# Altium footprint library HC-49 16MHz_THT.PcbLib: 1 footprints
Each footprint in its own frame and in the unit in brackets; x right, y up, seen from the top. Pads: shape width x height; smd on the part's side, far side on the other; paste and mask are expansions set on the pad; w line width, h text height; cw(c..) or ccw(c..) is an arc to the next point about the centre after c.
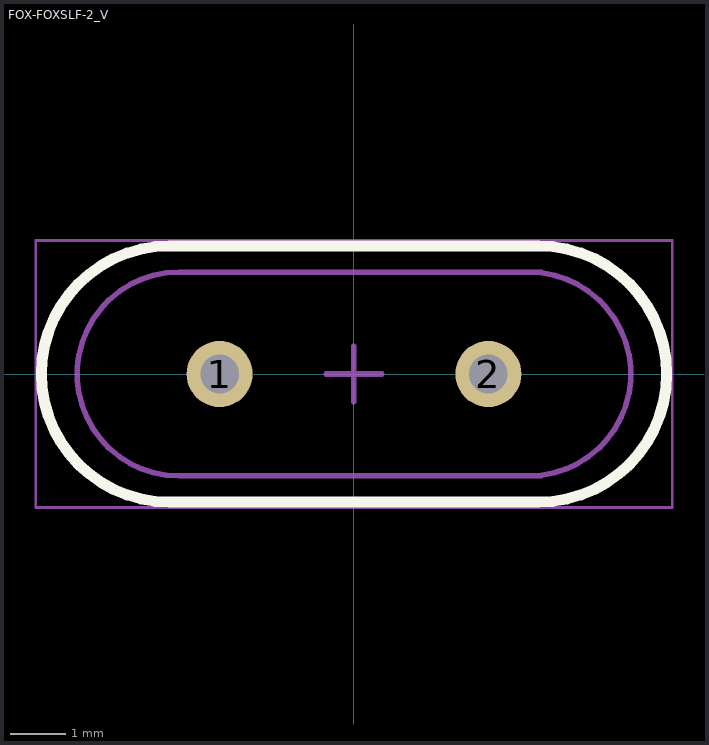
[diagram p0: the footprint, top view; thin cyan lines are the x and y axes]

## FOX-FOXSLF-2_V [mm] "THD, 2-Leads, Body 11.35x4.65mm, Pitch 4.88mm"
height 3.6
pads (2):
  round 1.2 hole 0.7: 1(-2.44,0) 2(2.44,0)
Top Overlay:
  lines w0.2: -3.35,-2.325 cw(c-3.35,0) -3.35,2.325 3.35,2.325 cw(c3.35,0) 3.35,-2.325 -3.35,-2.325
Mechanical 13:
  lines w0.1: 3.175,-1.85 ccw(c3.175,0) 3.175,1.85 ; 3.4,-1.85 -3.175,-1.85 cw(c-3.175,0) -3.175,1.85 3.4,1.85 ; -3.35,-2.325 cw(c-3.35,0) -3.35,2.325 3.35,2.325 cw(c3.35,0) 3.35,-2.325 -3.35,-2.325
Mechanical 15:
  lines w0.05: -5.775,-2.424 5.775,-2.424 5.775,2.425 -5.775,2.424 -5.775,-2.424
  lines w0.1: -0.5,0 0.5,0 ; 0,-0.5 0,0.5
3D body: height 3.6, standoff 0.5, extent -3.175,-1.85 3.175,1.85
3D body: height 3.6, standoff 0.5, extent 1.325,-1.85 5.025,1.85
3D body: height 3.6, standoff 0.5, extent -5.025,-1.849 -1.325,1.85
3D body: height 0.5, standoff 0, extent -3.35,-2.325 3.35,2.325
3D body: height 0.5, standoff 0, extent 1.025,-2.324 5.675,2.325
3D body: height 0.5, standoff 0, extent -5.675,-2.324 -1.025,2.324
